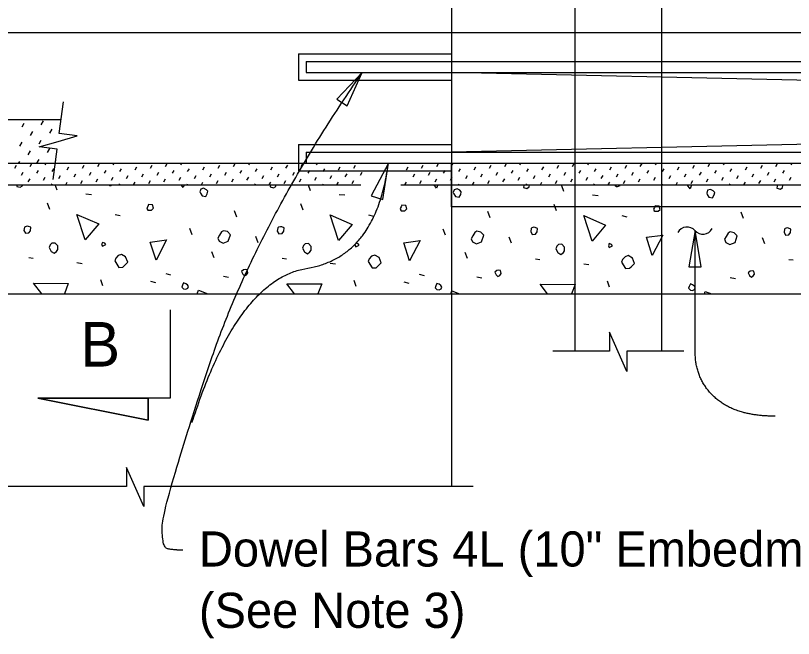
# Model space of a CAD drawing. Extents: x 0 to 41.1, y 0 to 26.
# Drawn here: x 27.706 to 32.167, y 8.281 to 11.855 of the extents above; entities that cross this region are included whole.
import ezdxf

# ---------------------------------------------------------------- set-up
doc = ezdxf.new("R2010")
doc.units = 0
for name, color, linetype in [('Dimension', 7, 'Continuous'), ('Miscellaneous', 7, 'Continuous'), ('Rebar', 7, 'Continuous'), ('TextStructures', 7, 'Continuous'), ('TrafBarrierConc', 7, 'Continuous')]:
    doc.layers.add(name, color=color, linetype=linetype)

msp = doc.modelspace()

# ---------------------------------------------------------------- linework, layer by layer
at = {"layer": 'Dimension'}
for p, q in [((28.5933, 10.1655), (28.5933, 9.6593)), ((28.5933, 9.6593), (27.8339, 9.6593)), ((27.8339, 9.6593), (28.4667, 9.5327)), ((28.4667, 9.5327), (28.4667, 9.6593))]:
    msp.add_line(p, q, dxfattribs=at)
for points in [[(29.6941, 11.5288), (29.5494, 11.3749), (29.6082, 11.3359)], [(29.8441, 11.008), (29.7452, 10.8213), (29.8122, 10.7992)], [(31.6033, 10.6209), (31.5682, 10.4127), (31.6387, 10.4127)], [(28.4667, 9.6593), (28.4667, 9.5327), (27.8339, 9.6593)]]:
    msp.add_lwpolyline(points, close=True, dxfattribs=at)
for points in [[(27.9212, 10.9146), (27.9443, 11.0884), (27.8419, 11.1021), (27.9503, 11.133), (28.0587, 11.1639), (27.9562, 11.1776), (27.9806, 11.36)], [(31.5378, 9.9291), (31.2125, 9.9291), (31.2125, 9.8128), (31.1131, 10.0378), (31.1131, 9.9291), (30.7878, 9.9291)], [(30.331, 9.1532), (28.441, 9.1532), (28.441, 9.037), (28.3416, 9.262), (28.3416, 9.1532), (27.061, 9.1532)]]:
    msp.add_lwpolyline(points, dxfattribs=at)
for centre, start, end in [((31.5572, 10.5821), 40.6168, 152.344), ((31.6477, 10.6597), 220.6168, 332.344)]:
    msp.add_arc(centre, 0.0596, start, end, dxfattribs=at)
for points in [[(28.6646, 8.7875), (28.6056, 8.7875), (28.5465, 8.8044), (28.5465, 9.0282), (29.0724, 10.6255), (29.6941, 11.5288)], [(28.7178, 9.5196), (28.9803, 10.3408), (29.7732, 10.4683), (29.8441, 11.008)], [(32.0632, 9.556), (31.8369, 9.556), (31.6033, 9.7642), (31.6033, 10.0931), (31.6033, 10.621)]]:
    msp.add_open_spline(points, degree=2, dxfattribs=at)
at = {"layer": 'Miscellaneous'}
for p, q in [((27.8537, 11.2286), (27.8667, 11.251)), ((27.7431, 11.2156), (27.756, 11.238)), ((27.9026, 11.1798), (27.9155, 11.2022)), ((27.7919, 11.1668), (27.8049, 11.1892)), ((27.7301, 11.105), (27.7431, 11.1274)), ((27.8408, 11.118), (27.8537, 11.1404)), ((27.779, 11.0562), (27.7919, 11.0786)), ((27.8896, 11.0691), (27.9026, 11.0915)), ((27.8278, 11.0073), (27.8408, 11.0297)), ((27.9384, 11.0203), (27.9389, 11.0211)), ((27.7013, 10.9788), (27.711, 10.9956)), ((27.7234, 11.0051), (27.7301, 11.0168)), ((27.7536, 11.007), (27.7532, 11.008)), ((27.7888, 10.9885), (27.7985, 11.0053)), ((27.8763, 10.9983), (27.8819, 11.008)), ((27.9152, 10.9594), (27.9249, 10.9762)), ((28.0027, 10.9691), (28.0124, 10.9859)), ((28.0902, 10.9788), (28.0999, 10.9956)), ((28.1777, 10.9885), (28.1874, 11.0053)), ((28.2652, 10.9983), (28.2708, 11.008)), ((28.3041, 10.9594), (28.3138, 10.9762)), ((28.3916, 10.9691), (28.4013, 10.9859)), ((28.4791, 10.9788), (28.4888, 10.9956)), ((28.5666, 10.9885), (28.5763, 11.0053)), ((28.6541, 10.9983), (28.6597, 11.008)), ((28.693, 10.9594), (28.7027, 10.9762)), ((28.7805, 10.9691), (28.7902, 10.9859)), ((28.868, 10.9788), (28.8777, 10.9956)), ((28.9555, 10.9885), (28.9652, 11.0053)), ((29.043, 10.9983), (29.0487, 11.008)), ((29.0819, 10.9594), (29.0916, 10.9762)), ((29.1694, 10.9691), (29.1791, 10.9859)), ((29.2569, 10.9788), (29.2666, 10.9956)), ((29.3444, 10.9885), (29.3542, 11.0053)), ((29.4319, 10.9983), (29.4376, 11.008)), ((29.4708, 10.9594), (29.4805, 10.9762)), ((29.5583, 10.9691), (29.5681, 10.9859)), ((29.6458, 10.9788), (29.6556, 10.9956)), ((29.9472, 10.9691), (29.957, 10.9859)), ((30.0347, 10.9788), (30.0445, 10.9956)), ((30.1222, 10.9885), (30.132, 11.0053)), ((30.2098, 10.9983), (30.2154, 11.008)), ((30.2486, 10.9594), (30.2584, 10.9762)), ((30.3361, 10.9691), (30.3459, 10.9859)), ((30.4237, 10.9788), (30.4334, 10.9956)), ((30.5112, 10.9885), (30.5209, 11.0053)), ((30.5987, 10.9983), (30.6043, 11.008)), ((30.6376, 10.9594), (30.6473, 10.9762)), ((30.7251, 10.9691), (30.7348, 10.9859)), ((30.8126, 10.9788), (30.8223, 10.9956)), ((30.9001, 10.9885), (30.9098, 11.0053)), ((30.9876, 10.9983), (30.9932, 11.008)), ((31.0265, 10.9594), (31.0362, 10.9762)), ((31.114, 10.9691), (31.1237, 10.9859)), ((31.2015, 10.9788), (31.2112, 10.9956)), ((31.289, 10.9885), (31.2987, 11.0053)), ((31.3765, 10.9983), (31.3821, 11.008)), ((31.4154, 10.9594), (31.4251, 10.9762)), ((31.5029, 10.9691), (31.5126, 10.9859)), ((31.5904, 10.9788), (31.6001, 10.9956)), ((31.6779, 10.9885), (31.6876, 11.0053)), ((31.7654, 10.9983), (31.771, 11.008)), ((31.8043, 10.9594), (31.814, 10.9762)), ((31.8918, 10.9691), (31.9015, 10.9859)), ((31.9793, 10.9788), (31.989, 10.9956)), ((32.0668, 10.9885), (32.0765, 11.0053)), ((32.1543, 10.9983), (32.1599, 11.008)), ((27.7402, 10.9399), (27.7499, 10.9567)), ((27.8277, 10.9496), (27.8374, 10.9664)), ((27.9541, 10.9205), (27.9638, 10.9373)), ((28.0416, 10.9302), (28.0513, 10.947)), ((28.1291, 10.9399), (28.1388, 10.9567)), ((28.2166, 10.9496), (28.2263, 10.9664)), ((28.343, 10.9205), (28.3527, 10.9373)), ((28.4305, 10.9302), (28.4402, 10.947)), ((28.518, 10.9399), (28.5277, 10.9567)), ((28.6055, 10.9496), (28.6152, 10.9664)), ((28.7319, 10.9205), (28.7416, 10.9373)), ((28.8194, 10.9302), (28.8291, 10.947)), ((28.9069, 10.9399), (28.9166, 10.9567)), ((28.9944, 10.9496), (29.0041, 10.9664)), ((29.1208, 10.9205), (29.1305, 10.9373)), ((29.2083, 10.9302), (29.218, 10.947)), ((29.2958, 10.9399), (29.3055, 10.9567)), ((29.3833, 10.9496), (29.393, 10.9664)), ((29.5097, 10.9205), (29.5194, 10.9373)), ((29.5972, 10.9302), (29.6069, 10.947)), ((29.6847, 10.9399), (29.6944, 10.9567)), ((29.9861, 10.9302), (29.9959, 10.947)), ((30.0736, 10.9399), (30.0834, 10.9567)), ((30.1611, 10.9496), (30.1709, 10.9664)), ((30.2875, 10.9205), (30.2973, 10.9373)), ((30.375, 10.9302), (30.3848, 10.947)), ((30.4625, 10.9399), (30.4723, 10.9567)), ((30.55, 10.9496), (30.5598, 10.9664)), ((30.6764, 10.9205), (30.6862, 10.9373)), ((30.7639, 10.9302), (30.7737, 10.947)), ((30.8515, 10.9399), (30.8612, 10.9567)), ((30.939, 10.9496), (30.9487, 10.9664)), ((31.0654, 10.9205), (31.0751, 10.9373)), ((31.1529, 10.9302), (31.1626, 10.947)), ((31.2404, 10.9399), (31.2501, 10.9567)), ((31.3279, 10.9496), (31.3376, 10.9664)), ((31.4543, 10.9205), (31.464, 10.9373)), ((31.5418, 10.9302), (31.5515, 10.947)), ((31.6293, 10.9399), (31.639, 10.9567)), ((31.7168, 10.9496), (31.7265, 10.9664)), ((31.8432, 10.9205), (31.8529, 10.9373)), ((31.9307, 10.9302), (31.9404, 10.947)), ((32.0182, 10.9399), (32.0279, 10.9567)), ((32.1057, 10.9496), (32.1154, 10.9664)), ((27.7791, 10.901), (27.7888, 10.9178)), ((27.8666, 10.9108), (27.8763, 10.9275)), ((27.9119, 10.883), (27.9152, 10.8887)), ((27.9938, 10.883), (28.0027, 10.8984)), ((28.0805, 10.8913), (28.0902, 10.9081)), ((28.168, 10.901), (28.1777, 10.9178)), ((28.2555, 10.9108), (28.2652, 10.9275)), ((28.3008, 10.883), (28.3041, 10.8887)), ((28.3827, 10.883), (28.3916, 10.8984)), ((28.4694, 10.8913), (28.4791, 10.9081)), ((28.5569, 10.901), (28.5666, 10.9178)), ((28.6444, 10.9108), (28.6541, 10.9275)), ((28.6897, 10.883), (28.693, 10.8887)), ((28.7716, 10.883), (28.7805, 10.8984)), ((28.8583, 10.8913), (28.868, 10.9081)), ((28.9458, 10.901), (28.9555, 10.9178)), ((29.0333, 10.9108), (29.043, 10.9275)), ((29.0786, 10.883), (29.0819, 10.8887)), ((29.1605, 10.883), (29.1694, 10.8984)), ((29.2472, 10.8913), (29.2569, 10.9081)), ((29.3347, 10.901), (29.3444, 10.9178)), ((29.4222, 10.9108), (29.4319, 10.9275)), ((29.4675, 10.883), (29.4708, 10.8887)), ((29.5494, 10.883), (29.5583, 10.8984)), ((29.6361, 10.8913), (29.6458, 10.9081)), ((29.9383, 10.883), (29.9472, 10.8984)), ((30.025, 10.8913), (30.0347, 10.9081)), ((30.1125, 10.901), (30.1222, 10.9178)), ((30.2, 10.9108), (30.2098, 10.9275)), ((30.2454, 10.883), (30.2486, 10.8887)), ((30.3272, 10.883), (30.3361, 10.8984)), ((30.4139, 10.8913), (30.4237, 10.9081)), ((30.5014, 10.901), (30.5112, 10.9178)), ((30.5889, 10.9108), (30.5987, 10.9275)), ((30.6343, 10.883), (30.6376, 10.8887)), ((30.7161, 10.883), (30.7251, 10.8984)), ((30.8028, 10.8913), (30.8126, 10.9081)), ((30.8903, 10.901), (30.9001, 10.9178)), ((30.9778, 10.9108), (30.9876, 10.9275)), ((31.0232, 10.883), (31.0265, 10.8887)), ((31.1051, 10.883), (31.114, 10.8984)), ((31.1917, 10.8913), (31.2015, 10.9081)), ((31.2792, 10.901), (31.289, 10.9178)), ((31.3668, 10.9108), (31.3765, 10.9275)), ((31.4121, 10.883), (31.4154, 10.8887)), ((31.494, 10.883), (31.5029, 10.8984)), ((31.5807, 10.8913), (31.5904, 10.9081)), ((31.6682, 10.901), (31.6779, 10.9178)), ((31.7557, 10.9108), (31.7654, 10.9275)), ((31.801, 10.883), (31.8043, 10.8887)), ((31.8829, 10.883), (31.8918, 10.8984)), ((31.9696, 10.8913), (31.9793, 10.9081)), ((32.0571, 10.901), (32.0668, 10.9178)), ((32.1446, 10.9108), (32.1543, 10.9275)), ((27.9449, 10.852), (27.9335, 10.883)), ((29.398, 10.8484), (29.3857, 10.882)), ((30.8511, 10.8449), (30.8388, 10.8785)), ((28.1093, 10.8325), (28.1411, 10.829)), ((29.5624, 10.829), (29.5943, 10.8254)), ((31.0155, 10.8254), (31.0474, 10.8219)), ((27.9025, 10.7424), (27.8884, 10.7777)), ((29.3556, 10.7388), (29.3415, 10.7742)), ((30.8087, 10.7353), (30.7946, 10.7706)), ((28.2773, 10.7141), (28.3055, 10.707)), ((28.9755, 10.6982), (28.9614, 10.7335)), ((29.7304, 10.7105), (29.7587, 10.7035)), ((30.4286, 10.6946), (30.4145, 10.73)), ((31.8817, 10.6911), (31.8676, 10.7264)), ((31.1835, 10.707), (31.2118, 10.6999)), ((28.7192, 10.5974), (28.7051, 10.6328)), ((30.1723, 10.5939), (30.1582, 10.6292)), ((29.0975, 10.5514), (29.0834, 10.5868)), ((30.5506, 10.5479), (30.5365, 10.5833)), ((32.0037, 10.5444), (31.9896, 10.5797)), ((28.8447, 10.4648), (28.8323, 10.4984)), ((30.2978, 10.4613), (30.2854, 10.4949)), ((27.7823, 10.4666), (27.807, 10.463)), ((29.2354, 10.463), (29.2601, 10.4595)), ((30.6885, 10.4595), (30.7132, 10.456)), ((32.1416, 10.456), (32.1664, 10.4524)), ((28.0581, 10.4383), (28.0881, 10.433)), ((29.5112, 10.4348), (29.5412, 10.4295)), ((30.9643, 10.4312), (30.9943, 10.4259)), ((28.5672, 10.3747), (28.5955, 10.3676)), ((28.8978, 10.3587), (28.9278, 10.3534)), ((30.0203, 10.3711), (30.0486, 10.3641)), ((30.3509, 10.3552), (30.3809, 10.3499)), ((31.804, 10.3517), (31.834, 10.3464)), ((28.2066, 10.3039), (28.1942, 10.3375)), ((28.4806, 10.3305), (28.5088, 10.3234)), ((29.6597, 10.3004), (29.6473, 10.334)), ((29.9337, 10.3269), (29.9619, 10.3199)), ((31.1128, 10.2969), (31.1004, 10.3305))]:
    msp.add_line(p, q, dxfattribs=at)
for points in [[(31.4128, 9.9291), (31.4128, 13.6579), (30.9128, 13.6579), (30.9128, 9.9291)], [(27.7133, 10.8749), (27.7328, 10.8696), (27.7452, 10.8785), (27.7458, 10.883)], [(27.7145, 10.883), (27.7133, 10.8749)], [(28.2427, 10.883), (28.2454, 10.8802)], [(28.2454, 10.8802), (28.2525, 10.8802), (28.258, 10.883)], [(28.6679, 10.8679), (28.6565, 10.883)], [(28.6736, 10.883), (28.6679, 10.8679)], [(28.7669, 10.836), (28.7758, 10.8201), (28.797, 10.8166), (28.8058, 10.8325), (28.8094, 10.8467), (28.8005, 10.8555), (28.7846, 10.8643), (28.7687, 10.859), (28.7634, 10.8431), (28.7669, 10.836)], [(29.1665, 10.8714), (29.1859, 10.8661), (29.1983, 10.8749), (29.1994, 10.883)], [(29.1681, 10.883), (29.1665, 10.8714)], [(30.121, 10.8643), (30.1069, 10.883)], [(30.128, 10.883), (30.121, 10.8643)], [(30.22, 10.8325), (30.2289, 10.8166), (30.2501, 10.8131), (30.2589, 10.829), (30.2625, 10.8431), (30.2536, 10.852), (30.2377, 10.8608), (30.2218, 10.8555), (30.2165, 10.8396), (30.22, 10.8325)], [(30.6196, 10.8679), (30.639, 10.8626), (30.6514, 10.8714), (30.653, 10.883)], [(30.6217, 10.883), (30.6213, 10.8802), (30.6196, 10.8679)], [(31.1437, 10.883), (31.1446, 10.8802), (31.1517, 10.8732)], [(31.1517, 10.8732), (31.1587, 10.8732), (31.1729, 10.8802), (31.1738, 10.883)], [(31.5742, 10.8608), (31.5573, 10.883)], [(31.5824, 10.883), (31.5742, 10.8608)], [(31.6731, 10.829), (31.682, 10.8131), (31.7032, 10.8095), (31.712, 10.8254), (31.7156, 10.8396), (31.7067, 10.8484), (31.6908, 10.8573), (31.6749, 10.852), (31.6696, 10.836), (31.6731, 10.829)], [(32.0727, 10.8643), (32.0921, 10.859), (32.1045, 10.8679), (32.1062, 10.8802), (32.1035, 10.883)], [(32.0753, 10.883), (32.0744, 10.8767), (32.0727, 10.8643)], [(28.4646, 10.7388), (28.4859, 10.7388), (28.4965, 10.7494), (28.4912, 10.7689), (28.4682, 10.7706), (28.4646, 10.76), (28.4593, 10.7512), (28.4646, 10.7388), (28.4611, 10.7424)], [(29.9178, 10.7353), (29.939, 10.7353), (29.9496, 10.7459), (29.9443, 10.7653), (29.9213, 10.7671), (29.9178, 10.7565), (29.9124, 10.7477), (29.9178, 10.7353), (29.9142, 10.7388)], [(31.3709, 10.7317), (31.3921, 10.7317), (31.4027, 10.7424), (31.3974, 10.7618), (31.3744, 10.7636), (31.3709, 10.753), (31.3656, 10.7441), (31.3709, 10.7317), (31.3673, 10.7353)], [(28.1058, 10.5673), (28.0581, 10.7141), (28.1836, 10.6593), (28.1058, 10.5673)], [(29.5589, 10.5638), (29.5112, 10.7105), (29.6367, 10.6557), (29.5589, 10.5638)], [(31.012, 10.5603), (30.9643, 10.707), (31.0898, 10.6522), (31.012, 10.5603)], [(27.754, 10.6221), (27.7628, 10.6062), (27.7823, 10.608), (27.7911, 10.6204), (27.7929, 10.6398), (27.7805, 10.6451), (27.7717, 10.6469), (27.7611, 10.6434), (27.7575, 10.6398), (27.754, 10.6221)], [(28.873, 10.5603), (28.896, 10.5479), (28.926, 10.5603), (28.9384, 10.5974), (28.9207, 10.6151), (28.8978, 10.6204), (28.8871, 10.6133), (28.8748, 10.5939), (28.8659, 10.578), (28.873, 10.5603)], [(29.2071, 10.6186), (29.2159, 10.6027), (29.2354, 10.6045), (29.2442, 10.6168), (29.246, 10.6363), (29.2336, 10.6416), (29.2248, 10.6434), (29.2142, 10.6398), (29.2106, 10.6363), (29.2071, 10.6186)], [(30.6602, 10.6151), (30.6691, 10.5992), (30.6885, 10.6009), (30.6973, 10.6133), (30.6991, 10.6328), (30.6867, 10.6381), (30.6779, 10.6398), (30.6673, 10.6363), (30.6638, 10.6328), (30.6602, 10.6151)], [(32.1133, 10.6115), (32.1222, 10.5956), (32.1416, 10.5974), (32.1504, 10.6098), (32.1522, 10.6292), (32.1398, 10.6345), (32.131, 10.6363), (32.1204, 10.6328), (32.1169, 10.6292), (32.1133, 10.6115)], [(30.3261, 10.5567), (30.3491, 10.5444), (30.3791, 10.5567), (30.3915, 10.5939), (30.3738, 10.6115), (30.3509, 10.6168), (30.3402, 10.6098), (30.3279, 10.5903), (30.319, 10.5744), (30.3261, 10.5567)], [(31.3572, 10.478), (31.3236, 10.5823), (31.4173, 10.5947), (31.3572, 10.478)], [(31.7792, 10.5532), (31.8022, 10.5408), (31.8322, 10.5532), (31.8446, 10.5903), (31.8269, 10.608), (31.804, 10.6133), (31.7934, 10.6062), (31.781, 10.5868), (31.7721, 10.5709), (31.7792, 10.5532)], [(27.899, 10.5232), (27.9096, 10.5019), (27.9272, 10.4913), (27.9414, 10.5019), (27.9485, 10.5125), (27.9485, 10.5338), (27.9326, 10.5497), (27.9131, 10.5479), (27.9043, 10.5391), (27.899, 10.5232)], [(28.2048, 10.532), (28.2242, 10.5408), (28.2172, 10.5479), (28.2048, 10.5532), (28.1995, 10.5408), (28.2048, 10.532)], [(28.5124, 10.4507), (28.4788, 10.555), (28.5725, 10.5673), (28.5124, 10.4507)], [(29.3521, 10.5196), (29.3627, 10.4984), (29.3804, 10.4878), (29.3945, 10.4984), (29.4016, 10.509), (29.4016, 10.5302), (29.3857, 10.5461), (29.3662, 10.5444), (29.3574, 10.5355), (29.3521, 10.5196)], [(29.6579, 10.5285), (29.6773, 10.5373), (29.6703, 10.5444), (29.6579, 10.5497), (29.6526, 10.5373), (29.6579, 10.5285)], [(29.9655, 10.4471), (29.9319, 10.5514), (30.0256, 10.5638), (29.9655, 10.4471)], [(30.8052, 10.5161), (30.8158, 10.4949), (30.8335, 10.4843), (30.8476, 10.4949), (30.8547, 10.5055), (30.8547, 10.5267), (30.8388, 10.5426), (30.8193, 10.5408), (30.8105, 10.532), (30.8052, 10.5161)], [(31.111, 10.5249), (31.1304, 10.5338), (31.1234, 10.5408), (31.111, 10.5461), (31.1057, 10.5338), (31.111, 10.5249)], [(28.2755, 10.4471), (28.2985, 10.41), (28.3215, 10.4118), (28.3303, 10.4206), (28.3497, 10.4401), (28.3374, 10.4701), (28.3126, 10.4843), (28.2949, 10.4772), (28.2808, 10.463), (28.2755, 10.4471)], [(29.7286, 10.4436), (29.7516, 10.4065), (29.7746, 10.4082), (29.7834, 10.4171), (29.8028, 10.4365), (29.7905, 10.4666), (29.7657, 10.4807), (29.748, 10.4737), (29.7339, 10.4595), (29.7286, 10.4436)], [(31.1817, 10.4401), (31.2047, 10.4029), (31.2277, 10.4047), (31.2365, 10.4135), (31.256, 10.433), (31.2436, 10.463), (31.2188, 10.4772), (31.2012, 10.4701), (31.187, 10.456), (31.1817, 10.4401)], [(29.0091, 10.3711), (29.0197, 10.3605), (29.0303, 10.3676), (29.0374, 10.3782), (29.0339, 10.3959), (29.025, 10.3976), (29.0127, 10.3959), (29.002, 10.3853), (29.0091, 10.3711)], [(30.4622, 10.3676), (30.4728, 10.357), (30.4834, 10.3641), (30.4905, 10.3747), (30.487, 10.3923), (30.4781, 10.3941), (30.4658, 10.3923), (30.4552, 10.3817), (30.4622, 10.3676)], [(31.9153, 10.3641), (31.9259, 10.3534), (31.9365, 10.3605), (31.9436, 10.3711), (31.9401, 10.3888), (31.9312, 10.3906), (31.9189, 10.3888), (31.9083, 10.3782), (31.9153, 10.3641)], [(27.8558, 10.258), (27.8088, 10.3199), (28.0086, 10.3181), (27.9861, 10.258)], [(28.6697, 10.2863), (28.6821, 10.2845), (28.6945, 10.2898), (28.698, 10.3004), (28.6927, 10.3093), (28.6821, 10.3163), (28.6697, 10.3216), (28.6626, 10.3075), (28.6591, 10.2969), (28.6697, 10.2863)], [(29.3062, 10.258), (29.2619, 10.3163), (29.4617, 10.3146), (29.4405, 10.258)], [(30.1228, 10.2827), (30.1352, 10.281), (30.1476, 10.2863), (30.1511, 10.2969), (30.1458, 10.3057), (30.1352, 10.3128), (30.1228, 10.3181), (30.1157, 10.3039), (30.1122, 10.2933), (30.1228, 10.2827)], [(30.7567, 10.258), (30.715, 10.3128), (30.9148, 10.311), (30.895, 10.258)], [(31.5759, 10.2792), (31.5883, 10.2774), (31.6007, 10.2827), (31.6042, 10.2933), (31.5989, 10.3022), (31.5883, 10.3093), (31.5759, 10.3146), (31.5688, 10.3004), (31.5653, 10.2898), (31.5759, 10.2792)], [(28.748, 10.258), (28.7546, 10.2792), (28.8081, 10.258)], [(30.2022, 10.258), (30.2077, 10.2757), (30.2523, 10.258)], [(31.6564, 10.258), (31.6608, 10.2721), (31.6965, 10.258)]]:
    msp.add_lwpolyline(points, dxfattribs=at)
at = {"layer": 'Rebar'}
for p, q in [((29.3726, 11.5913), (33.0081, 11.5913)), ((29.3726, 11.5913), (29.3726, 11.5288)), ((29.3726, 11.5288), (33.0081, 11.5288)), ((33.0081, 11.4664), (30.2059, 11.5288)), ((33.0081, 11.1329), (30.2059, 11.0705)), ((29.3726, 11.0705), (33.0081, 11.0705)), ((29.3726, 11.0705), (29.3726, 11.008)), ((29.3726, 11.008), (33.0081, 11.008))]:
    msp.add_line(p, q, dxfattribs=at)
at = {"layer": 'TrafBarrierConc'}
for p, q in [((30.2059, 13.6746), (30.2059, 11.008)), ((27.186, 11.758), (33.2059, 11.758)), ((29.3281, 11.6358), (29.3281, 11.4844)), ((29.3281, 11.6358), (30.2059, 11.6358)), ((29.3281, 11.4844), (30.2059, 11.4844)), ((27.1859, 11.258), (27.967, 11.258)), ((29.3281, 11.1149), (29.3281, 10.9635)), ((29.3281, 11.1149), (30.2059, 11.1149)), ((27.186, 11.008), (29.7451, 11.008)), ((29.9154, 11.008), (35.0443, 11.008)), ((30.206, 11.0079), (30.206, 9.1532)), ((29.3281, 10.9635), (30.2059, 10.9635)), ((27.206, 10.883), (29.6855, 10.883)), ((29.9154, 10.883), (35.0495, 10.883)), ((27.206, 10.258), (35.0443, 10.258))]:
    msp.add_line(p, q, dxfattribs=at)
msp.add_lwpolyline([(33.2059, 11.758), (33.2059, 10.758), (30.2059, 10.758), (30.2059, 11.008)], dxfattribs=at)

# ---------------------------------------------------------------- texts
at = {"layer": 'Dimension'}
for s, p in [('Dowel Bars 4L (10" Embedment)', (28.7577, 8.6934)), ('(See Note 3)', (28.7577, 8.3414))]:
    msp.add_text(s, height=0.2016, dxfattribs=at).set_placement(p)
at = {"layer": 'TextStructures'}
msp.add_text('B', height=0.256, dxfattribs=at).set_placement((28.0773, 9.8405))

doc.saveas('drawing.dxf')
